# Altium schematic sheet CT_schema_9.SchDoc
size 278 x 170 mm
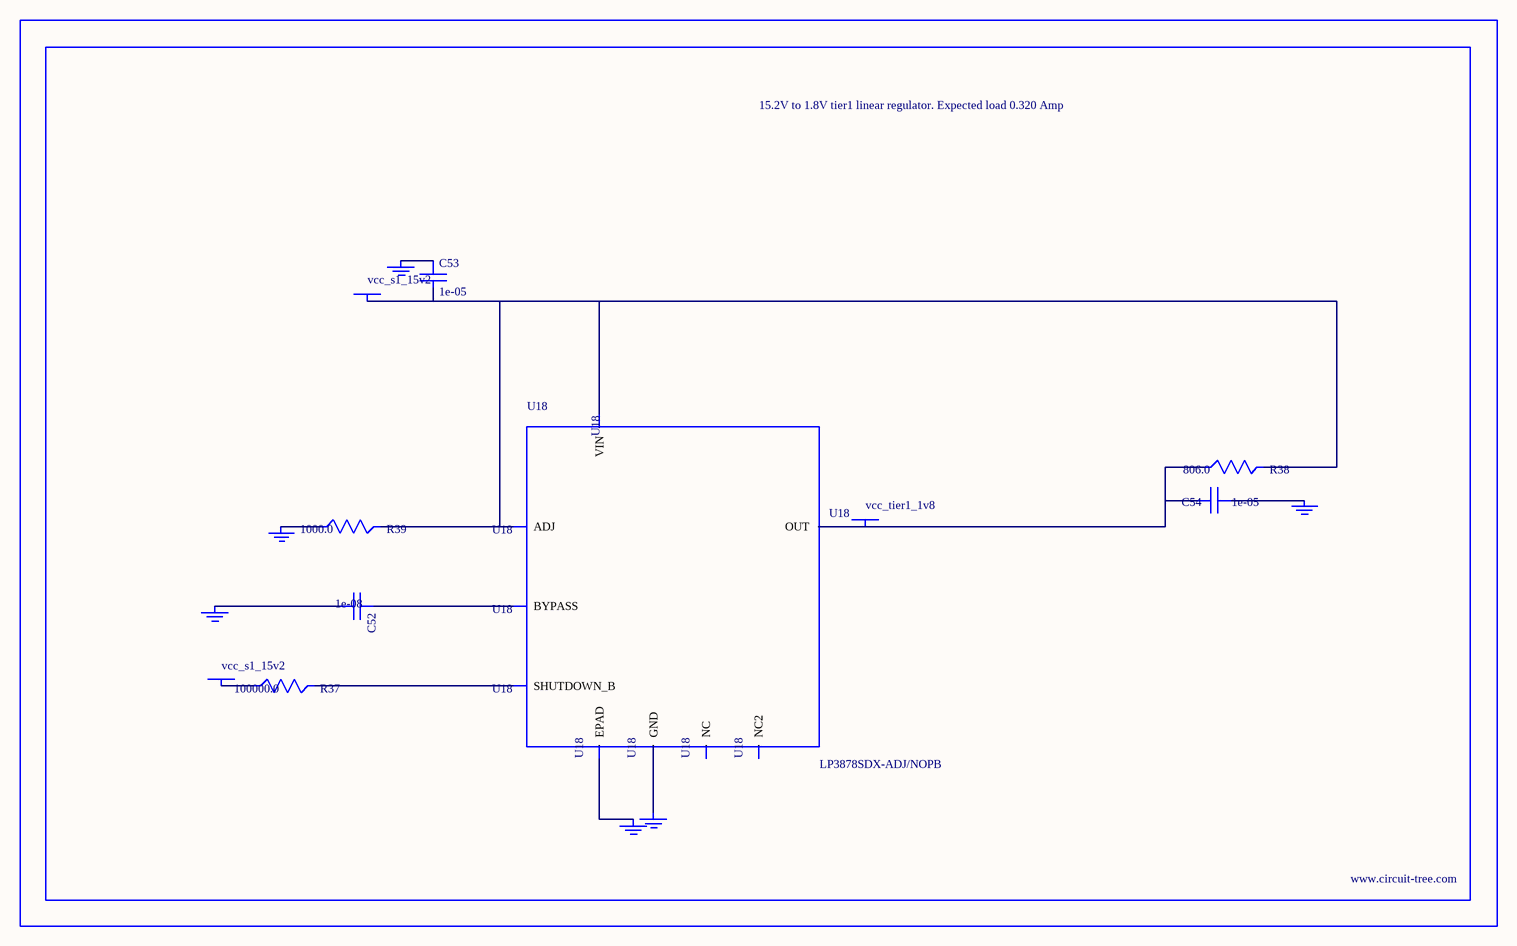
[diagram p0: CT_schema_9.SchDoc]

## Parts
BORDER8  (no value)
C52  1e-08  [C0402]
C53  1e-05  [C1210]
C54  1e-05  [C0805]
GND_INSTANCE_8_0  (no value)
GND_INSTANCE_8_1  (no value)
GND_INSTANCE_8_2  (no value)
GND_INSTANCE_8_3  (no value)
GND_INSTANCE_8_4  (no value)
GND_INSTANCE_8_5  (no value)
POWER_INSTANCE_8_0  vcc_s1_15v2
POWER_INSTANCE_8_1  vcc_s1_15v2
POWER_INSTANCE_8_2  vcc_tier1_1v8
R37  100000.0  [R0603]
R38  806.0  [R0603]
R39  1000.0  [R0603]
U18  LP3878SDX-ADJ/NOPB  [WSON-8]

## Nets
NetC52_1: C52.1 U18.1(BYPASS)
NetC52_2: C52.2 GND_INSTANCE_8_0.0(GND)
NetC53_1: C53.1 GND_INSTANCE_8_1.0(GND)
NetC53_2: C53.2 POWER_INSTANCE_8_0.0(PWR) R38.2 R39.2 U18.4(VIN) U18.6(ADJ)
NetC54_1: C54.1 GND_INSTANCE_8_2.0(GND)
NetC54_2: C54.2 POWER_INSTANCE_8_2.0(PWR) R38.1 U18.5(OUT)
NetGND_INSTANCE_8_3_0: GND_INSTANCE_8_3.0(GND) R39.1
NetGND_INSTANCE_8_4_0: GND_INSTANCE_8_4.0(GND) U18.PAD(EPAD)
NetGND_INSTANCE_8_5_0: GND_INSTANCE_8_5.0(GND) U18.3(GND)
NetPOWER_INSTANCE_8_1_0: POWER_INSTANCE_8_1.0(PWR) R37.1
NetR37_2: R37.2 U18.8(SHUTDOWN_B)

Not connected (* = marked no-connect by the designer): U18 2(NC) 7(NC2)

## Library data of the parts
BORDER8 = BORDER_PAGE8
C52 = C0402C103K3RAC
C53 = C1210C106K5PACTU
C54 = GRM219R60J106ME19D
GND_INSTANCE_8_0-GND_INSTANCE_8_5 = GND
POWER_INSTANCE_8_0-POWER_INSTANCE_8_2 = PWR
R37 = RC0603JR-07100KL
R38 = ERJ-3EKF8060V
R39 = RC0603JR-071KL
